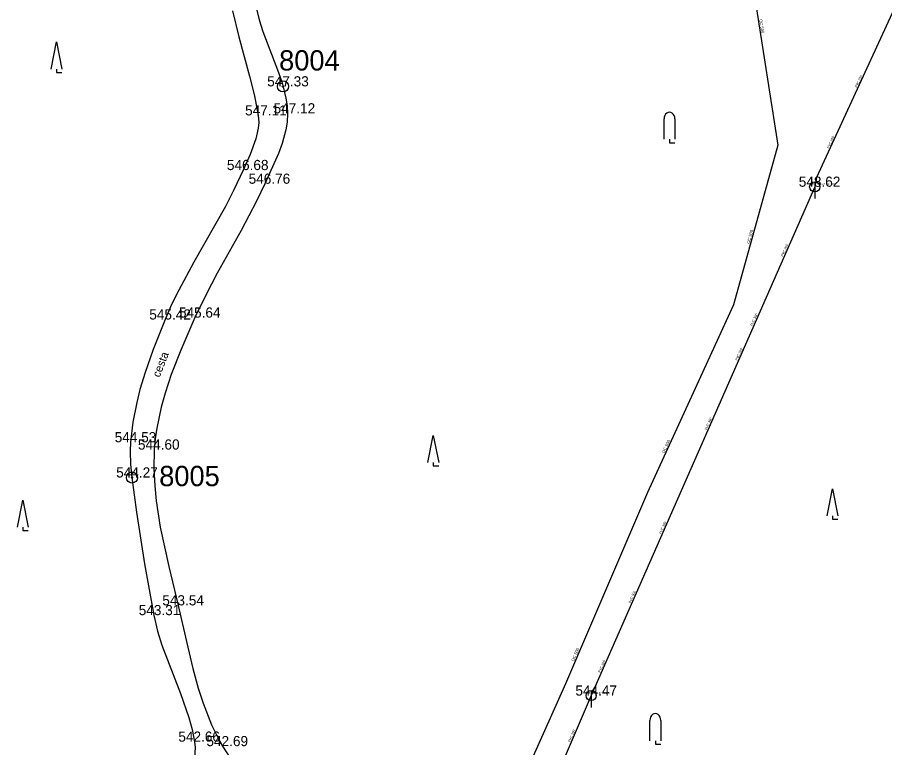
# Model space of a CAD drawing. Extents: x -669393 to -668650, y -1126925 to -1126294.
# Drawn here: x -669103.1 to -669039.1, y -1126614.5 to -1126560.7 of the extents above; entities that cross this region are included whole.
import ezdxf

# ---------------------------------------------------------------- set-up
doc = ezdxf.new("R2010")
doc.units = 0
for name, color, linetype in [('G_Bod_tecka', 7, 'Continuous'), ('G_Bod_vyska', 7, 'Continuous'), ('G_Bodove_pole', 7, 'Continuous'), ('G_Cesty_Schody', 7, 'Continuous'), ('G_Popisy_povrchu', 7, 'Continuous'), ('G_Site-kanalizace', 7, 'Continuous'), ('G_Z_KANAL_podz_kotovane', 7, 'Continuous'), ('G_Z_VODA_podz_kotovane', 7, 'Continuous'), ('G_Zelen-Znacky', 7, 'Continuous'), ('Vrstva 12', 7, 'Continuous'), ('Vrstva 2', 7, 'Continuous'), ('Vrstva 26', 7, 'Continuous'), ('Vrstva 3', 7, 'Continuous'), ('Vrstva 4', 7, 'Continuous'), ('Vrstva 8', 7, 'Continuous')]:
    doc.layers.add(name, color=color, linetype=linetype)

msp = doc.modelspace()

# ---------------------------------------------------------------- linework, layer by layer
at = {"layer": 'G_Bod_tecka'}
for p, q in [((-669083.5, -1126565.75), (-669083.5, -1126565.75)), ((-669085.33, -1126567.89), (-669085.33, -1126567.89)), ((-669083.17, -1126567.74), (-669083.17, -1126567.74)), ((-669086.44, -1126571.92), (-669086.44, -1126571.92)), ((-669084.84, -1126572.93), (-669084.84, -1126572.93)), ((-669044.3, -1126573.15), (-669044.3, -1126573.15)), ((-669092.19, -1126582.94), (-669092.19, -1126582.94)), ((-669089.99, -1126582.8), (-669089.99, -1126582.8)), ((-669094.74, -1126591.99), (-669094.74, -1126591.99)), ((-669092.99, -1126592.53), (-669092.99, -1126592.53)), ((-669094.63, -1126594.59), (-669094.63, -1126594.59)), ((-669091.23, -1126604.02), (-669091.23, -1126604.02)), ((-669093.03, -1126604.74), (-669093.03, -1126604.74)), ((-669060.78, -1126610.67), (-669060.78, -1126610.67)), ((-669090.02, -1126614.07), (-669090.02, -1126614.07)), ((-669087.96, -1126614.4), (-669087.96, -1126614.4))]:
    msp.add_line(p, q, dxfattribs=at)
at = {"layer": 'G_Bodove_pole'}
for centre, radius in [((-669083.5, -1126565.75), 0.412), ((-669083.5, -1126565.75), 0.05), ((-669094.63, -1126594.59), 0.412), ((-669094.63, -1126594.59), 0.05)]:
    msp.add_circle(centre, radius, dxfattribs=at)
at = {"layer": 'G_Cesty_Schody'}
for points in [[(-669087.21, -1126560.17), (-669086.75, -1126562.1), (-669085.96, -1126565), (-669085.61, -1126566.44), (-669085.33, -1126567.89), (-669085.29, -1126568.4), (-669085.32, -1126568.84), (-669085.49, -1126569.61), (-669085.93, -1126570.77), (-669086.44, -1126571.92), (-669087.11, -1126573.37), (-669087.73, -1126574.6), (-669090.06, -1126578.71), (-669091.18, -1126580.78), (-669091.71, -1126581.84), (-669092.19, -1126582.94), (-669093.07, -1126585.16), (-669093.66, -1126586.84), (-669094.04, -1126588.11), (-669094.28, -1126589.07), (-669094.57, -1126590.52), (-669094.74, -1126591.99), (-669094.76, -1126592.64), (-669094.73, -1126593.62), (-669094.63, -1126594.59), (-669094.3, -1126597.14), (-669093.7, -1126600.96), (-669093.03, -1126604.74), (-669092.75, -1126605.93), (-669092.42, -1126606.96), (-669091.05, -1126610.51), (-669090.43, -1126612.29), (-669090.19, -1126613.18), (-669090.02, -1126614.07), (-669089.98, -1126614.5), (-669090.01, -1126615.27)], [(-669085.49, -1126559.83), (-669085.26, -1126560.83), (-669084.98, -1126561.7), (-669083.82, -1126564.72), (-669083.57, -1126565.48), (-669083.29, -1126566.61), (-669083.2, -1126567.17), (-669083.17, -1126567.74), (-669083.2, -1126568.39), (-669083.29, -1126568.96), (-669083.57, -1126569.96), (-669083.84, -1126570.7), (-669084.84, -1126572.93), (-669085.45, -1126574.22), (-669086.59, -1126576.38), (-669088.34, -1126579.53), (-669089.19, -1126581.14), (-669089.99, -1126582.8), (-669091.03, -1126585.19), (-669091.74, -1126587), (-669092.19, -1126588.37), (-669092.48, -1126589.4), (-669092.81, -1126590.96), (-669092.92, -1126591.74), (-669092.99, -1126592.53), (-669093.02, -1126593.96), (-669092.95, -1126595.21), (-669092.84, -1126596.31), (-669092.54, -1126598.24), (-669091.92, -1126601.14), (-669091.23, -1126604.02), (-669090.62, -1126606.69), (-669090.15, -1126608.67), (-669089.74, -1126610.13), (-669089.39, -1126611.22), (-669088.76, -1126612.83), (-669088.38, -1126613.62), (-669087.96, -1126614.4), (-669087.41, -1126615.23)]]:
    msp.add_lwpolyline(points, dxfattribs=at)
at = {"layer": 'G_Site-kanalizace'}
for points in [[(-669044.3, -1126572.775), (-669044.3, -1126574.025)], [(-669060.78, -1126610.295), (-669060.78, -1126611.545)]]:
    msp.add_lwpolyline(points, dxfattribs=at)
for centre in [(-669044.3, -1126573.15), (-669060.78, -1126610.67)]:
    msp.add_circle(centre, 0.375, dxfattribs=at)
at = {"layer": 'G_Z_KANAL_podz_kotovane'}
msp.add_line((-669044.3, -1126573.15), (-669060.78, -1126610.67), dxfattribs=at)
for points in [[(-669023.63, -1126516.4), (-669023.55, -1126516.75), (-669021.94, -1126523.9), (-669026.15, -1126533.31), (-669044.17, -1126572.46), (-669044.3, -1126573.15)], [(-669060.78, -1126610.67), (-669072.87, -1126638.89), (-669075.05, -1126644.14), (-669076.65, -1126647.54)]]:
    msp.add_lwpolyline(points, dxfattribs=at)
at = {"layer": 'G_Z_VODA_podz_kotovane'}
msp.add_lwpolyline([(-669048.66, -1126559.56), (-669047.02, -1126570.09), (-669050.28, -1126581.86), (-669056.62, -1126595.69), (-669062.68, -1126609.81), (-669072.18, -1126631.09), (-669079.53, -1126640.12), (-669084.75, -1126644.7), (-669088.99, -1126648.51), (-669092.4, -1126651.82), (-669093.31, -1126658.95), (-669094.79, -1126673.58)], dxfattribs=at)
at = {"layer": 'G_Zelen-Znacky'}
for p, q in [((-669100.59, -1126564.47), (-669100.19, -1126562.47)), ((-669100.19, -1126562.47), (-669099.79, -1126564.47)), ((-669100.19, -1126564.47), (-669100.19, -1126564.72)), ((-669100.19, -1126564.72), (-669099.79, -1126564.72))]:
    msp.add_line(p, q, dxfattribs=at)
for points in [[(-669055.41, -1126569.65), (-669055.41, -1126568.15)], [(-669054.61, -1126568.15), (-669054.61, -1126569.65)], [(-669055.01, -1126569.65), (-669055.01, -1126569.9)], [(-669055.01, -1126569.9), (-669054.61, -1126569.9)], [(-669072.82, -1126593.48), (-669072.42, -1126591.48)], [(-669072.42, -1126591.48), (-669072.02, -1126593.48)], [(-669072.42, -1126593.48), (-669072.42, -1126593.73)], [(-669072.42, -1126593.73), (-669072.02, -1126593.73)], [(-669043.39, -1126597.42), (-669042.99, -1126595.42)], [(-669042.99, -1126595.42), (-669042.59, -1126597.42)], [(-669103.08, -1126598.25), (-669102.68, -1126596.25)], [(-669102.68, -1126596.25), (-669102.28, -1126598.25)], [(-669042.99, -1126597.42), (-669042.99, -1126597.67)], [(-669042.99, -1126597.67), (-669042.59, -1126597.67)], [(-669102.68, -1126598.25), (-669102.68, -1126598.5)], [(-669102.68, -1126598.5), (-669102.28, -1126598.5)], [(-669056.45, -1126614), (-669056.45, -1126612.5)], [(-669055.65, -1126612.5), (-669055.65, -1126614)], [(-669056.05, -1126614), (-669056.05, -1126614.25)], [(-669056.05, -1126614.25), (-669055.65, -1126614.25)]]:
    msp.add_lwpolyline(points, dxfattribs=at)
for centre in [(-669055.01, -1126568.15), (-669056.05, -1126612.5)]:
    msp.add_ellipse(centre, major_axis=(0, 0.5), ratio=0.8, start_param=4.712389, end_param=7.853982, dxfattribs=at)
at = {"layer": 'Vrstva 12'}
msp.add_line((-669044.3, -1126573.15), (-669060.78, -1126610.67), dxfattribs=at)
for points in [[(-669023.631, -1126516.402), (-669023.552, -1126516.751), (-669021.939, -1126523.895), (-669026.149, -1126533.31), (-669044.169, -1126572.456), (-669044.3, -1126573.15)], [(-669060.78, -1126610.67), (-669072.87, -1126638.89), (-669075.05, -1126644.14), (-669076.65, -1126647.54)]]:
    msp.add_lwpolyline(points, dxfattribs=at)
at = {"layer": 'Vrstva 26'}
msp.add_lwpolyline([(-669048.66, -1126559.56), (-669047.02, -1126570.09), (-669050.28, -1126581.86), (-669056.62, -1126595.69), (-669062.68, -1126609.81), (-669072.177, -1126631.087), (-669079.531, -1126640.118), (-669084.749, -1126644.702), (-669088.993, -1126648.512), (-669092.402, -1126651.82), (-669093.314, -1126658.954), (-669094.785, -1126673.584)], dxfattribs=at)
at = {"layer": 'Vrstva 8'}
for p, q in [((-669044.3, -1126573.15), (-669044.3, -1126573.15)), ((-669060.78, -1126610.67), (-669060.78, -1126610.67))]:
    msp.add_line(p, q, dxfattribs=at)

# ---------------------------------------------------------------- texts
at = {"layer": 'G_Bod_vyska'}
for s, p in [('547.33', (-669084.664, -1126565.75)), ('547.11', (-669086.291, -1126567.89)), ('547.12', (-669084.192, -1126567.74)), ('546.68', (-669087.632, -1126571.92)), ('546.76', (-669086.032, -1126572.93)), ('548.62', (-669045.478, -1126573.15)), ('545.42', (-669093.354, -1126582.94)), ('545.64', (-669091.168, -1126582.8)), ('544.53', (-669095.904, -1126591.99)), ('544.60', (-669094.189, -1126592.53)), ('544.27', (-669095.794, -1126594.59)), ('543.54', (-669092.394, -1126604.02)), ('543.31', (-669094.132, -1126604.74)), ('544.47', (-669061.944, -1126610.67)), ('542.66', (-669091.212, -1126614.07)), ('542.69', (-669089.14, -1126614.4))]:
    msp.add_text(s, height=0.75, dxfattribs=at).set_placement(p)
at = {"layer": 'G_Bodove_pole'}
for s, p in [('8004', (-669083.783, -1126564.58)), ('8005', (-669092.623, -1126595.23))]:
    msp.add_text(s, height=1.5, dxfattribs=at).set_placement(p)
at = {"layer": 'G_Popisy_povrchu'}
msp.add_text('cesta', height=0.6, rotation=68.69721, dxfattribs=at).set_placement((-669092.598, -1126587.25))
at = {"layer": 'Vrstva 2'}
for s, p in [('548.62 (544.88)', (-669044.095, -1126573.028)), ('544.47 (541.7)', (-669060.574, -1126610.548))]:
    msp.add_text(s, height=0.13163, dxfattribs=at).set_placement(p)
at = {"layer": 'Vrstva 3'}
for s, rotation, p in [('PVC 200', 65.21536, (-669041.19, -1126565.858)), ('PVC 200', 65.24385, (-669043.257, -1126570.348)), ('PVC 300', 66.31026, (-669046.645, -1126578.315)), ('PVC 300', 66.25175, (-669048.89, -1126583.426)), ('PVC 300', 66.27913, (-669050.012, -1126585.983)), ('PVC 300', 66.24802, (-669052.258, -1126591.095)), ('PVC 300', 66.28291, (-669055.626, -1126598.764)), ('PVC 300', 66.24802, (-669057.871, -1126603.876)), ('PVC 300', 66.27913, (-669060.118, -1126608.988)), ('PVC 300', 66.77911, (-669062.333, -1126614.114))]:
    msp.add_text(s, height=0.1755, rotation=rotation, dxfattribs=at).set_placement(p)
at = {"layer": 'Vrstva 4'}
for rotation, p in [(278.87303, (-669048.393, -1126560.815)), (74.57681, (-669049.11, -1126577.372)), (65.38463, (-669055.385, -1126592.826)), (66.75273, (-669062.055, -1126608.175))]:
    msp.add_text('OC 500', height=0.2194, rotation=rotation, dxfattribs=at).set_placement(p)

doc.saveas('drawing.dxf')
